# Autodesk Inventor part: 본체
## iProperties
Created: 2015-01
Part Number: 본체
Material: 알루미늄-6061
Document SubType Name: Modeling
Designer: elite
Mass: 1021.16 g
Surface Area: 1059.8 cm^2
Volume: 376.813 cm^3
Density: 2.71 g/cm^3
Author: elite
